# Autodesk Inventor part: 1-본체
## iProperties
Created: 2014-12
Part Number: 1-본체
Document SubType Name: Modeling
Designer: Administrator
Density: 2.71 g/cm^3
Material: 알루미늄-6061
Mass: 613.126 g
Surface Area: 666.029 cm^2
Volume: 226.246 cm^3
Author: Administrator
